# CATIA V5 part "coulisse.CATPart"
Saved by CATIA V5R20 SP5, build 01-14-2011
Part number: coulisse
Publications: "distance Ab", "trou oblong haut", "Longueur", "Face", "Esquisse.2"
Bounding box of the stored display mesh (mm): x 0 to 20, y -94.409 to -64.409, z -455.74 to -170
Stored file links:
  M:\EU_thinkMotion\IAO_2010\iao\IAO_MMS_Groupe2\IAO_MMS_Groupe2\rwatrin\rwatrin\coulisse.CATPart
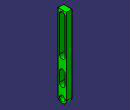
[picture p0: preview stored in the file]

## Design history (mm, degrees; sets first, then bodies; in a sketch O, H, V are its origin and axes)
Parameters
  Longueur = 270 mm
  `trou oblong haut` = 125.356 mm
  `trou oblong bas` = 35.816 mm
  `distance entre trou` = 50 mm
  `distance Ab` = 43.53 mm
Body1 (main body)
  Sketch1 on yz-plane, origin (0, 0, 0), H (0, 1, 0), V (0, 0, 1)
    line L1 (-94.4094, -170) -> (-64.4094, -170)
    line L2 (-64.4094, -170) -> (-64.4094, -440.7397)
    arc A1 centre (-79.4094, -440.7397) radius 15 from (-64.4094, -440.7397) to (-94.4094, -440.7397) cw
    line L3 (-94.4094, -440.7397) -> (-94.4094, -170)
    line L4 (-89.4094, -396.47) -> (-89.4094, -360.654)
    arc A2 centre (-79.4094, -360.654) radius 10 from (-89.4094, -360.654) to (-69.4094, -360.654) cw
    line L5 (-69.4094, -360.654) -> (-69.4094, -396.47)
    arc A3 centre (-79.4094, -396.47) radius 10 from (-69.4094, -396.47) to (-89.4094, -396.47) cw
    point P12 (-89.4094, -185.298)
    line L6 (-89.4094, -185.298) -> (-89.4094, -310.654)
    arc A4 centre (-79.4094, -310.654) radius 10 from (-89.4094, -310.654) to (-69.4094, -310.654) ccw
    point P15 (-69.4094, -310.654)
    line L7 (-69.4094, -310.654) -> (-69.4094, -185.298)
    arc A5 centre (-79.4094, -185.298) radius 10 from (-69.4094, -185.298) to (-89.4094, -185.298) ccw
    circle A6 centre (-79.4094, -440.7397) radius 10
    point P18 (-69.4094, -440.7397)
    radius A6 = 10
    radius A5 = 10
    distance L6 L7 = 20
    radius A2 = 10
    distance L7 L2 = 5
    distance L3 L6 = 5
    distance A6 L2 = 5
    horizontal: L1 H
    tangency: A1 L2, A2 L4, L5 A2, A3 L4, A3 L5, L6 A2, A4 L5, A4 L6, L7 A4, A5 L4, A5 L7
    vertical: L4 V
    coincidence: P12 L4, P15 L5, A6 P18
  Pad1: profile Sketch1, direction (1, 0, 0), length 20
  Sketch2 on end face of Pad1, origin (20, 0, 0), H (0, 1, 0), V (0, 0, 1)
    line L1 (-79.4094, -185.298) -> (-79.4094, -310.654)
    point P1 (-79.4094, -185.298)
    point P2 (-79.4094, -310.654)
    reference projected arc E1 centre (-79.4094, -185.298) radius 10 from (-69.4094, -185.298) to (-89.4094, -185.298) ccw from edge [end face of Pad1 | face of Pad1 from Sketch1.A5]
    reference projected arc E2 centre (-79.4094, -310.654) radius 10 from (-89.4094, -310.654) to (-69.4094, -310.654) ccw from edge [end face of Pad1 | face of Pad1 from Sketch1.A4]
    vertical: L1 V
    concentricity: E1 P1, P2 E2
  Sketch3 on end face of Pad1, origin (20, 0, 0), H (0, 1, 0), V (0, 0, 1)
    line L1 (-79.4094, -360.654) -> (-79.4094, -396.47)
    point P1 (-79.4094, -360.654)
    point P2 (-79.4094, -396.47)
    reference projected arc E1 centre (-79.4094, -360.654) radius 10 from (-69.4094, -360.654) to (-89.4094, -360.654) ccw from edge [end face of Pad1 | face of Pad1 from Sketch1.A2]
    reference projected arc E2 centre (-79.4094, -396.47) radius 10 from (-89.4094, -396.47) to (-69.4094, -396.47) ccw from edge [end face of Pad1 | face of Pad1 from Sketch1.A3]
    vertical: L1 V
    concentricity: P1 E1, P2 E2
